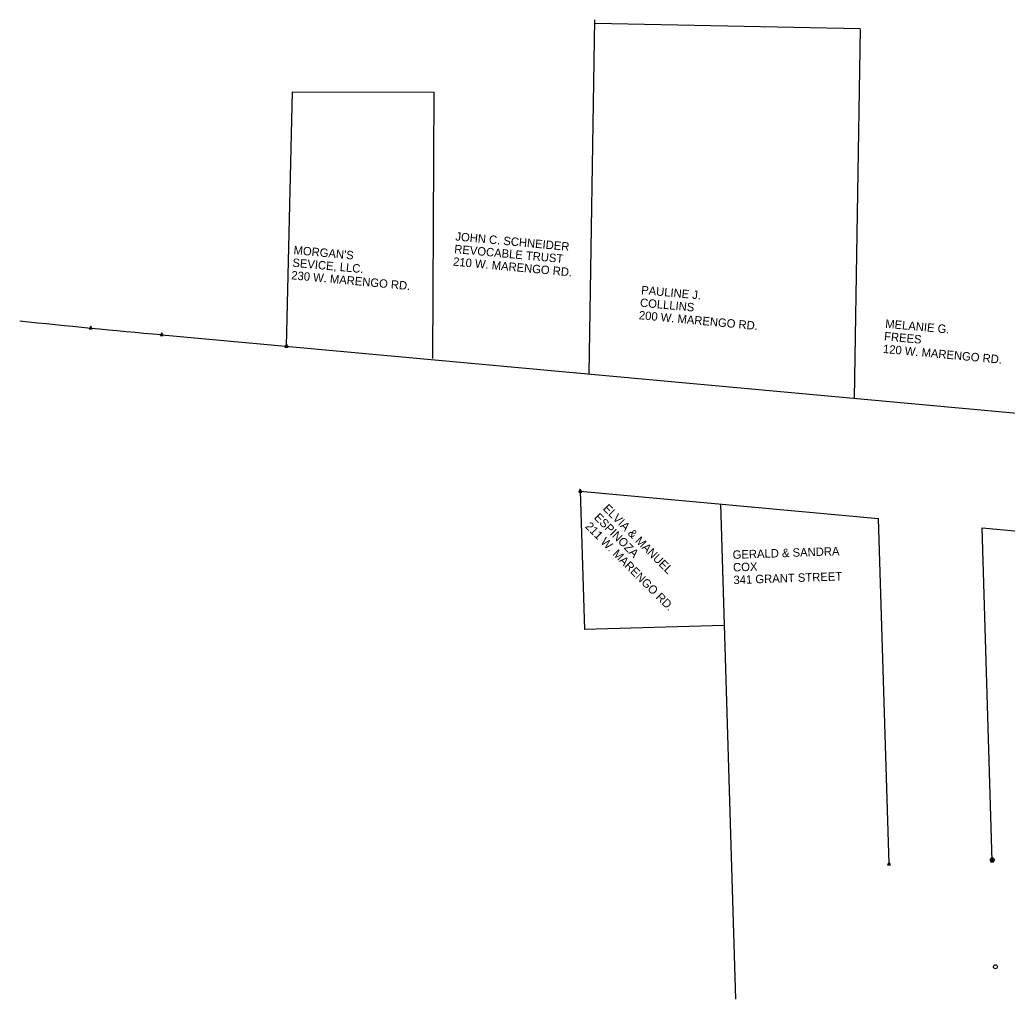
# Model space of a CAD drawing. Extents: x 20500076 to 20505422, y 7951999 to 7957351.
# Drawn here: x 20500076 to 20500631, y 7953693 to 7954242 of the extents above; entities that cross this region are included whole.
import ezdxf

# ---------------------------------------------------------------- set-up
doc = ezdxf.new("R2010")
doc.units = 0
for name, color, linetype in [('DisROW Existing', 7, 'Continuous'), ('DisROW Property Lines', 7, 'Continuous'), ('rowdsnSymbolsProposed', 7, 'Continuous'), ('SurControl', 7, 'Continuous'), ('SurPointsNonDTM', 7, 'Continuous'), ('SurSectionCorner', 7, 'Continuous'), ('Text', 7, 'Continuous')]:
    doc.layers.add(name, color=color, linetype=linetype)

msp = doc.modelspace()

# ---------------------------------------------------------------- linework, layer by layer
at = {"layer": 'DisROW Existing'}
for p in [(20500391.37, 7953977.79), (20500564.75, 7953768.48)]:
    msp.add_line(p, (20500558.89, 7953962.44), dxfattribs=at)
for points in [[(20500156.22, 7954065.61), (20500908.59, 7953996.67), (20500962.39, 7953992.58)], [(20500622.72, 7953770.22), (20500617.08, 7953957.11), (20500756.81, 7953944.3), (20500761.71, 7953774.91)]]:
    msp.add_lwpolyline(points, dxfattribs=at)
msp.add_arc((20500665.28, 7959721.75), 5679, 264.04903, 264.8572, dxfattribs=at)
at = {"layer": 'DisROW Property Lines'}
for p, q in [((20500396.38, 7954043.61), (20500399.59, 7954242.4)), ((20500548.52, 7954237.36), (20500399.55, 7954240.37)), ((20500548.52, 7954237.36), (20500545.18, 7954029.97)), ((20500391.37, 7953977.79), (20500393.72, 7953900.03)), ((20500470.06, 7953970.58), (20500478.44, 7953692.51)), ((20500472.11, 7953902.41), (20500393.72, 7953900.03))]:
    msp.add_line(p, q, dxfattribs=at)
msp.add_lwpolyline([(20500226.35, 7954059.19), (20500229.72, 7954202.01), (20500309.04, 7954201.67), (20500308.41, 7954052.17)], dxfattribs=at)
at = {"layer": 'rowdsnSymbolsProposed'}
for points in [[(20500076.49, 7954073.36), (20500076.5, 7954073.36)], [(20500116.34, 7954069.34), (20500116.35, 7954069.35)], [(20500156.22, 7954065.61), (20500156.22, 7954065.62)], [(20500226.35, 7954059.19), (20500226.36, 7954059.19)], [(20500308.41, 7954052.17), (20500308.41, 7954052.17)], [(20500396.38, 7954043.61), (20500396.39, 7954043.61)], [(20500545.18, 7954029.97), (20500545.18, 7954029.98)]]:
    msp.add_lwpolyline(points, dxfattribs=at)
at = {"layer": 'SurControl'}
for centre in [(20500622.7, 7953770.79), (20500624.56, 7953710.72)]:
    msp.add_circle(centre, 1.12, dxfattribs=at)
at = {"layer": 'SurPointsNonDTM'}
msp.add_circle((20500391.37, 7953977.79), 0.5, dxfattribs=at)
at = {"layer": 'SurSectionCorner'}
for points in [[(20500115.43, 7954068.82), (20500117.26, 7954068.82), (20500116.34, 7954070.4)], [(20500155.31, 7954065.09), (20500157.14, 7954065.09), (20500156.22, 7954066.67)], [(20500225.44, 7954058.66), (20500227.27, 7954058.66), (20500226.35, 7954060.24)], [(20500390.46, 7953977.26), (20500392.29, 7953977.26), (20500391.37, 7953978.85)], [(20500563.83, 7953767.95), (20500565.66, 7953767.95), (20500564.75, 7953769.53)], [(20500621.8, 7953769.7), (20500623.63, 7953769.7), (20500622.72, 7953771.28)]]:
    msp.add_lwpolyline(points, close=True, dxfattribs=at)

# ---------------------------------------------------------------- texts
at = {"layer": 'Text'}
for s, height, rotation, p in [('JOHN C. SCHNEIDER', 4.7244, 354.7645, (20500321.04, 7954118.5)), ("MORGAN'S ", 4.724, 354.7645, (20500230.14, 7954110.84)), ('REVOCABLE TRUST', 4.7244, 354.7645, (20500320.4, 7954111.44)), ('SEVICE, LLC.', 4.7244, 354.7645, (20500229.5, 7954103.78)), ('210 W. MARENGO RD.', 4.7244, 354.7645, (20500319.75, 7954104.39)), ('230 W. MARENGO RD.', 4.7244, 354.7645, (20500228.85, 7954096.72)), ('PAULINE J.', 4.724, 354.7645, (20500425.39, 7954088.41)), ('COLLLINS', 4.724, 354.7645, (20500424.75, 7954081.35)), ('200 W. MARENGO RD.', 4.7244, 354.7645, (20500424.1, 7954074.3)), ('MELANIE G.', 4.724, 354.7645, (20500562.49, 7954069.51)), ('FREES', 4.724, 354.7645, (20500561.84, 7954062.45)), ('120 W. MARENGO RD.', 4.7244, 354.7645, (20500561.2, 7954055.39)), ('ELVIA & MANUEL', 4.7244, 314.9836, (20500403.75, 7953967.63)), ('ESPINOZA', 4.724, 314.9836, (20500398.74, 7953962.62)), ('211 W. MARENGO RD.', 4.7244, 314.9836, (20500393.73, 7953957.61)), ('GERALD & SANDRA', 4.7244, 1.9645, (20500476.99, 7953939.71)), ('COX', 4.724, 1.9645, (20500477.23, 7953932.63)), ('341 GRANT STREET', 4.7244, 1.9645, (20500477.47, 7953925.55))]:
    msp.add_text(s, height=height, rotation=rotation, dxfattribs=at).set_placement(p)

doc.saveas('drawing.dxf')
